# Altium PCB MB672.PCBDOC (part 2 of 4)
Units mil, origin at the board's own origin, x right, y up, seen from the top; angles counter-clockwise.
Board outline 4505 x 6805 mil, 4 copper layers (TopLayer, GND, VCC, BottomLayer); 337 components, 289 nets, 1516 pads, 621 vias.
Unrouted connection lines stored in the file: 46.
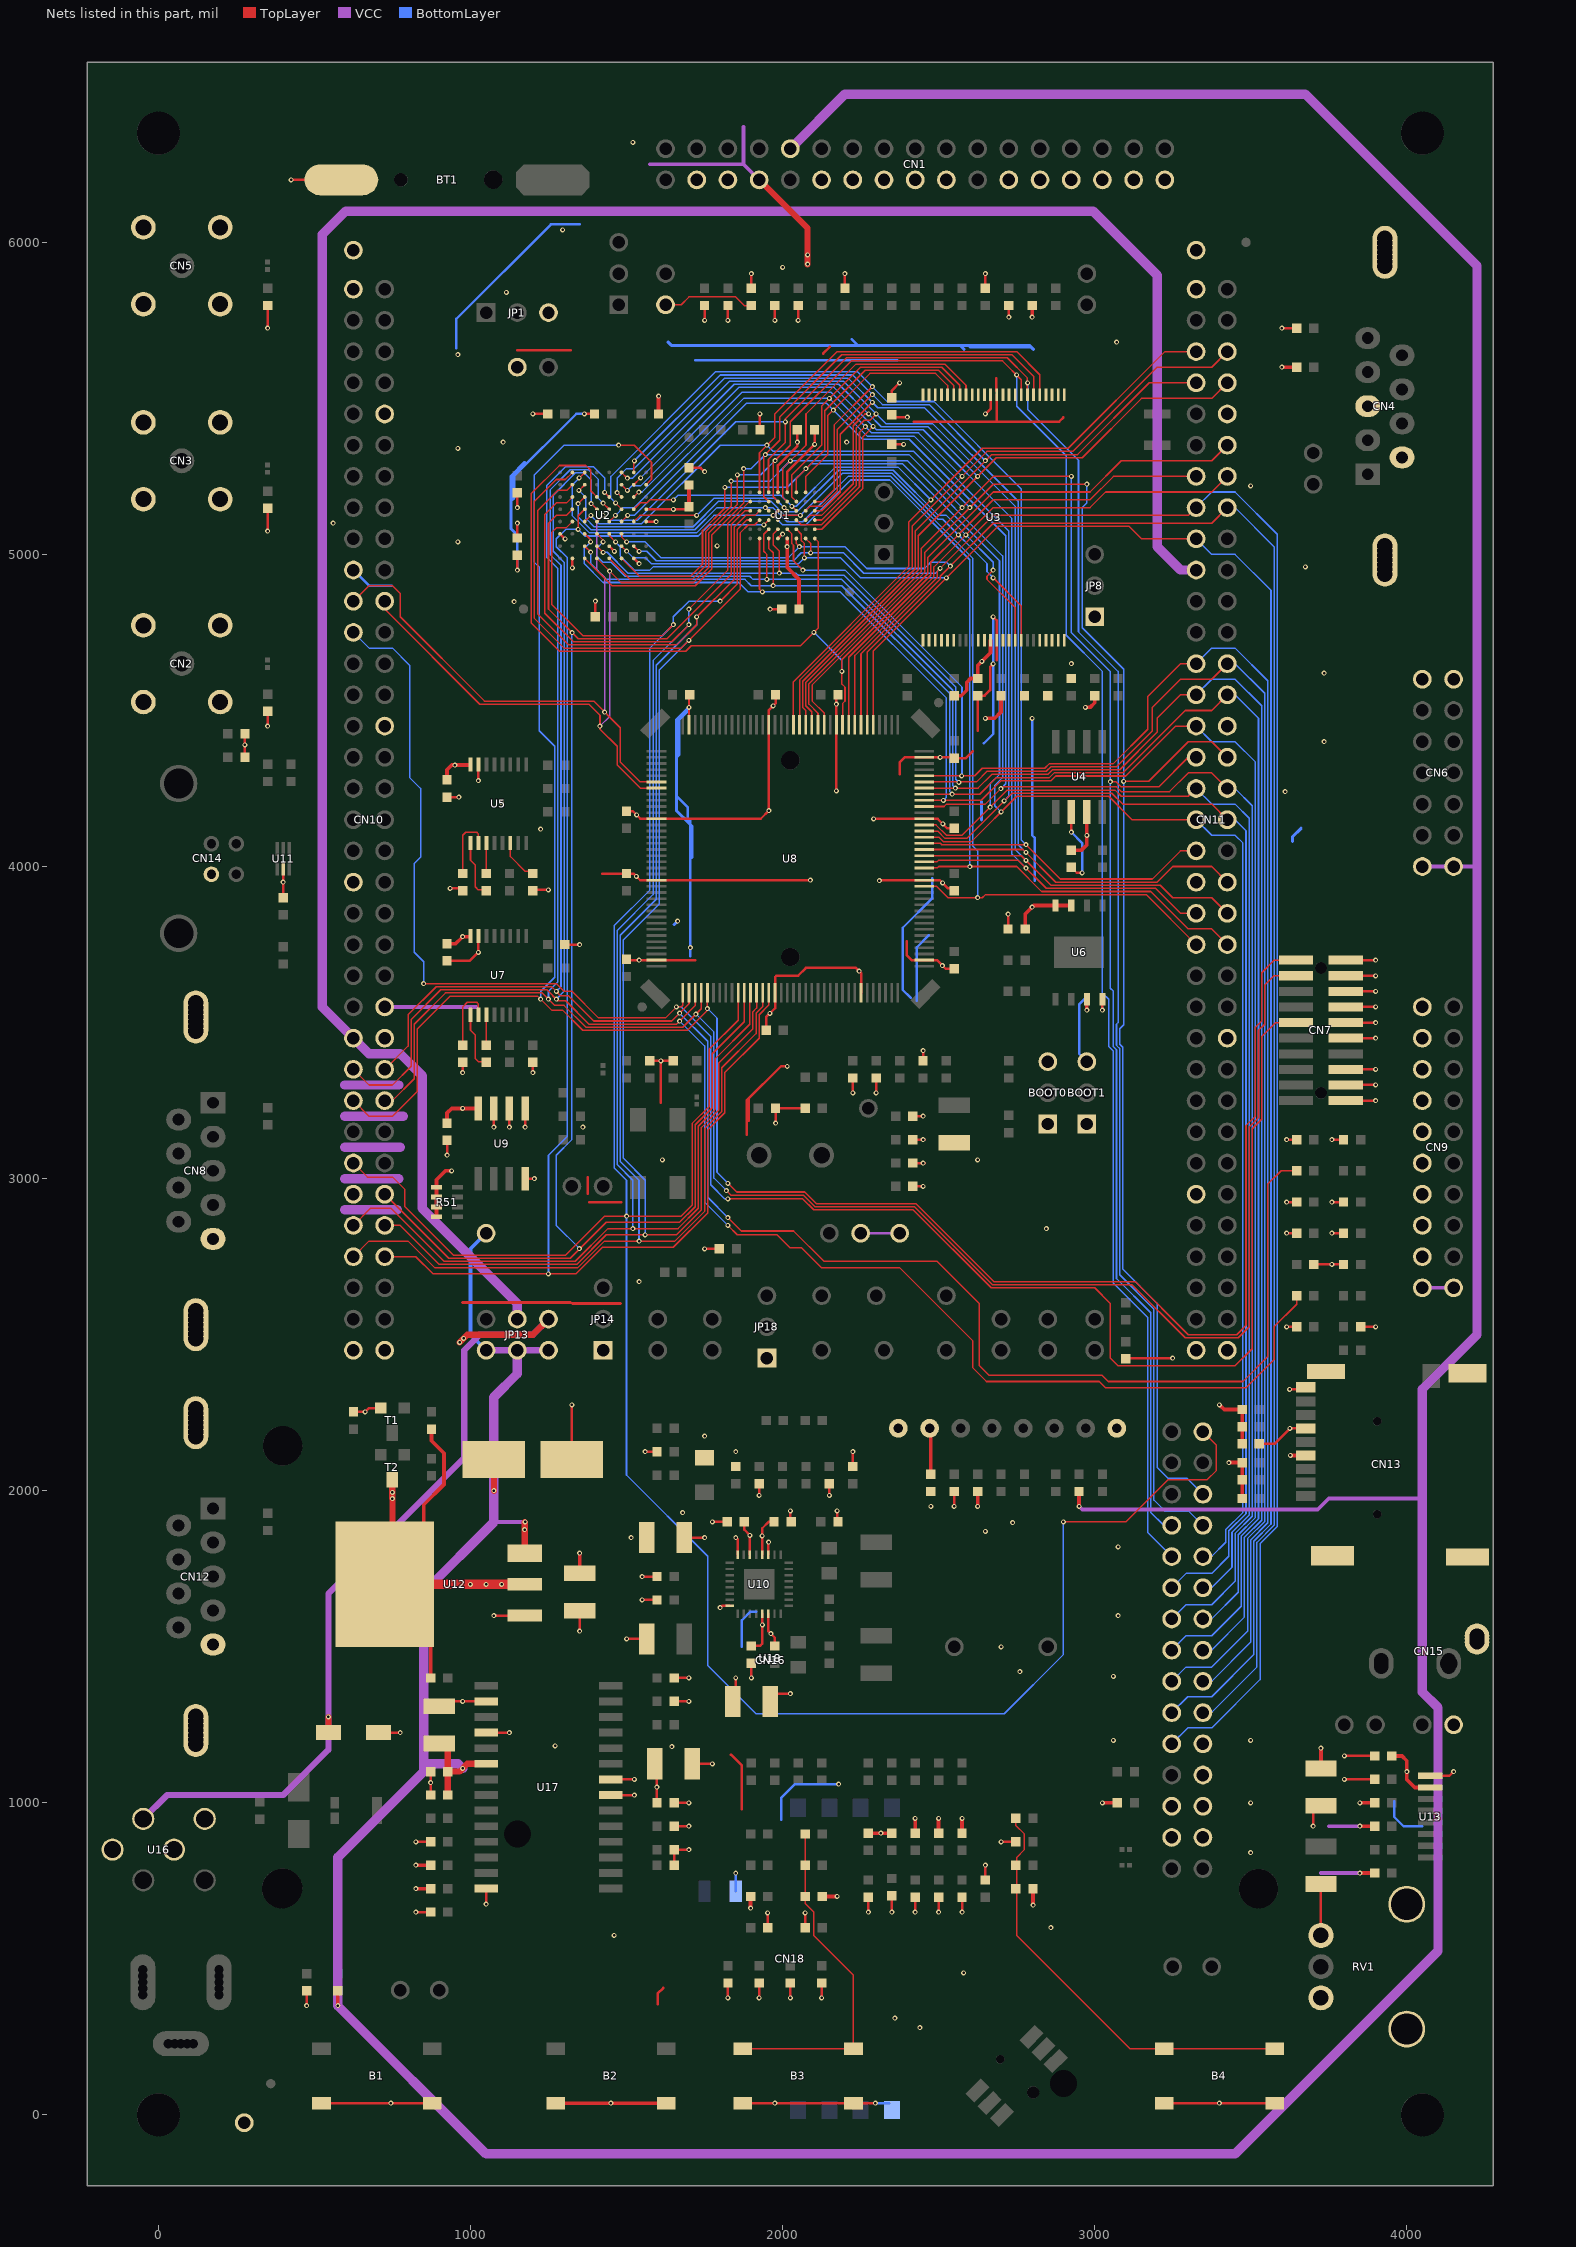
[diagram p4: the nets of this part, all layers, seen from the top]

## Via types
v1: diameter 16, hole 8, TopLayer to BottomLayer, tented both sides, 621 vias

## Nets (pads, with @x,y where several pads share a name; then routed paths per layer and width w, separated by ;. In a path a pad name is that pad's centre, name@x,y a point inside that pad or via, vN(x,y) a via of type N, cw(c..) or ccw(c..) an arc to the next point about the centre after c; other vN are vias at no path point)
+3V3: B2.1 B2.4 BOOT0.1 BOOT1.1 C11.1 C12.1 C14.2 C15.2 C16.1 C20.2 C24.2 C27.2 C34.2 C37.1 C49.2 C52.1 C62.2 C63.2 C64.1 C65.1 C68.1 C69.1 C71.1 C75.2 C79.1 C84.1 C88.2 CN1.28 CN7.1 CN9.1 CN9.2 CN10.48 CN10.69 CN11.69 CN13.4 CN16.24 CN16.25 CN16.28 JP1.3 JP12.2 R7.2 R10.1 R12.1 R13.2 R16.1 R17.2 R18.2 R19.1 R20.2 R23.2 R24.1 R27.2 R51.1 R51.3 R51.5 R51.7 R53.2 R55.2 R58.2 R59.2 R64.2 R66.2 R76.2 R83.2 R85.1 R88.2 R90.1 R91.1 R92.1 R93.1 R107.2 R109.1 R112.2 R113.1 R114.2 R115.2 R116.2 R118.1 R119.2 R120.1 R121.2 R122.2 R130.1 R131.1 R132.1 R133.1 R134.1 RV1.3 T2.3 TP5.1 U1.D6 U1.E1 U2.D8 U2.F1 U2.G5 U3.12 U3.37 U4.3 U5.16 U6.3 U6.7 U6.8 U7.16 U9.8 U10.4 U10.6 U10.8 U10.21 U12.2 U13.7 U17.21 U18.2 | length 8606.8
  TopLayer w8: v1@749.5,1975.5 v1(750,1975) ; C15.2@1150,5045 v1(1150,5100) ; v1(1150,5150) R18.2@1150,5197.5 ; v1(1200,5450) R12.1@1247.5,5450 ; U2.F1@1287.2,5065.94 v1(1303.15,5050) ; R20.2@1400,4800 v1(1400,4850) ; U2.G5@1444.68,5026.57 v1(1461.26,5010) ; U17.21@1450,1025 v1(1525,1025) ; v1(1550,1650) R83.2@1597.5,1650 ; U2.D8@1562.8,5144.69 R19.1@1704.68,5144.68 ; C88.2@1597.5,1000 C84.1@1597.5,1117.5 ; R93.1@1652.5,1325 v1(1700,1325) ; R91.1@1652.5,1400 v1(1700,1400) ; R109.1@1655,925 v1@1702.5,925 ; C65.1@1685,1850 v1(1750,1850) ; C79.1@1850,1340 v1(1850,1400) ; v1(1850,1850) 1856.1,1843.9 U10.8@1856.1,1794.49 ; C62.2@1877.5,1900 1877.5,1875 v1(1895.47,1857.03) U10.6@1895.47,1794.49 ; C75.2@1900,1502.5 1927.5,1502.5 1934.84,1509.84 U10.21@1934.84,1605.51 ; R16.1@1927.5,5400 v1(1927.5,5450) ; U10.4@1934.84,1794.49 1934.84,1879.84 1955,1900 C63.2@1972.5,1900 ; U1.D6@1985.24,5198.82 1985.24,5285.24 2047.5,5347.5 C12.1@2047.5,5400 ; R17.2@2350,5352.5 v1(2387.5,5352.5) ; C11.1@2350,5440 v1(2400,5440) ; v1(2650.1,5450.1) 2666.54,5466.54 U3.37@2666.54,5512.4 ; R58.2@3702.5,2725 R59.2@3797.5,2725 ; v1(3760,2825) R55.2@3797.5,2825 ; v1(3760,2925) R53.2@3797.5,2925 ; CN7.1@3805,3250 v1(3900,3250) ; R64.2@3852.5,2525 v1(3900,2525)
  TopLayer w12: v1(825,725) R119.2@872.5,725 ; v1(825,800) R118.1@872.5,800 ; U12.2@850,1880 850,1955 915,2020 915,2120 875,2160 R66.2@875,2197.5 ; R90.1@872.5,1400 U12.2@872.5,1527.5 ; R51.7@891.5,2877.76 891.5,2996.5 920,3025 v1(940,3025) ; C49.2@925,3177.5 925,3210 940,3225 U9.8@1025,3225 ; C37.1@925,3752.5 952.5,3752.5 v1(975,3775) U7.16@998.03,3775 ; C24.2@925,4277.5 925,4310 940,4325 U5.16@998.03,4325 ; B2.1@1272.83,37.5 B2.4@1627.17,37.5 ; C69.1@1350,1735 v1(1350,1800) ; R13.2@1602.5,5450 v1(1602.5,5507.5) ; R19.1@1700,5152.5 C14.2@1700,5222.5 ; v1(1897.5,662.5) R120.1@1897.5,700 ; U1.E1@2014.76,5051.18 2014.76,4957.74 2052.5,4920 C16.1@2052.5,4825 ; R121.2@2127.5,700 v1(2175,700) ; R112.2@2275,902.5 R113.1@2350,902.5 ; R114.2@2425,902.5 v1(2425,950) ; C64.1@2475,2052.5 U18.2@2475,2196.06 ; R115.2@2500,902.5 v1(2500,950) ; R23.2@2550,4547.5 2572.5,4547.5 2590,4565 2590,4590 2602.5,4602.5 C20.2@2625,4602.5 2625,4643.46 2666.54,4685 U3.12@2666.54,4725 ; R116.2@2575,902.5 v1(2575,950) ; v1(2625,1950) R76.2@2625,1997.5 ; v1(2650,4475) 2680,4475 2700,4495 R24.1@2700,4547.5 ; C34.2@2777.5,3800 2777.5,3847.5 2805,3875 U6.7@2925,3875 ; v1(2800,5760) R7.2@2800,5797.5 ; v1(2802.5,672.5) R122.2@2802.5,725 ; C27.2@2925,4052.5 2957.5,4052.5 2975,4070 U4.3@2975,4175 ; v1(2970,4510) 2985,4510 3000,4525 R27.2@3000,4547.5 ; v1(2975,3540) U6.3@2975,3575 ; v1(3025,1000) R107.2@3072.5,1000 ; v1(3400,2275) 3415,2260 R131.1@3472.5,2260 C52.1@3472.5,2150 ; v1(3430,2090) R134.1@3472.5,2090 R132.1@3472.5,1975 ; v1(3600,5600) R10.1@3647.5,5600 ; v1(3627.01,2112.99) CN13.4@3676.65,2112.99 ; C71.1@3725,1110 v1(3725,1175) ; v1(3850,775) R92.1@3897.5,775 ; v1(3850,925) R88.2@3897.5,925 ; v1(3850,1000) R85.1@3897.5,1000 ; C68.1@3952.5,1150 3985,1150 4000,1135 4000,1075 4025.59,1049.41 U13.7@4075,1049.41
  TopLayer w20: v1@749.5,1975.5 T2.3@749.5,2035 ; U12.2@750,1710 v1(750,1975) ; CN1.28@1925,6200 2080,6045 v1(2080,5930)
  TopLayer w30: U12.2@730,1700 U12.2@1173.82,1700
  VCC w8: JP12.2@2250,2825 TP5.1@2375,2825
  VCC w12: CN10.48@725,3550 1020,3550 ; 1575,6250 1875,6250 ; 1875,6370 1875,6250 ; CN1.28@1925,6200 1875,6250 ; 3725,775 v1(3850,775) ; 3750,925 v1(3850,925) ; CN9.2@4050,2650 CN9.1@4150,2650
  other v1: 1450,37.5 2315,902.5 1700,925 1597.5,1050 4000,1100 1935,1570 1000,1700 1050,1700 1100,1700 1934.84,1855 749.5,1995 3760,2725 975,3225 2800,3870 2975,4100 950,4325 2638.69,4657.15 2014.76,5025 1650,5144.69 2047.5,5360 2080,5960
+5V: C61.1 C82.1 C83.1 C86.1 CN1.25 CN6.1 CN6.2 JP13.1 JP13.3 JP13.5 R79.1 R127.2 TP4.1 U12.3 U17.6 | length 17048.1
  TopLayer w12: v1(575,350) R127.2@575,397.5 ; v1(2950,1950) R79.1@2950,1997.5
  TopLayer w20: C86.1@927.5,1025 C82.1@927.5,1187.5 ; C83.1@927.5,1100 965,1100 990,1125 U17.6@1050,1125 ; v1(1075,2000) C61.1@1075,2100 ; U12.3@1173.82,1800 v1@1173.82,1898.82
  VCC w12: 1075,1900 v1(1175,1900) ; v1(2950,1950) 2960,1940 3715,1940 3750,1975 4050,1975 ; CN6.2@4050,4000 4220,4000
  VCC w20: JP13.1@1050,2450 JP13.5@1250,2450
  VCC w30: 850,1125 960,1125 v1(975,1110) ; JP13.3@1150,2450 1150,2375 1075,2300 1075,1900 850,1675 850,1100 575,825 v1(575,350) 1050,-125 3450,-125 4100,525 4100,1305 4050,1355 4050,2325 4225,2500 4225,5925 3675,6475 2200,6475 CN1.25@2025,6300
  BottomLayer w12: JP13.1@1050,2450 1000,2500 1000,2775 TP4.1@1050,2825
  other v1: 1173.82,1875
A0: CN10.57 CN16.2 U1.A3 U2.E2 U8.10 | length 9253.4
  TopLayer w5: CN10.57@625,3050 670,3005 750,3005 790,2965 790,2910 945,2755 1305,2755 1430,2880 1675,2880 1710,2915 1710,3176.42 1765,3231.42 1765,3415 1857.68,3507.68 U8.10@1857.68,3595.87 ; U2.E2@1326.57,5105.32 1306.26,5085 1275,5085 1260,5070 1260,4840 1360,4740 1615,4740 v1(1649.93,4774.93) ; v1(1800,4850) 1855,4905 1855,5080 1885.24,5110.24 U1.A3@1896.65,5110.24 ; v1(2900,1900) 3100,1900 3235,2035 3360,2035 3390,2065 3390,2146 CN16.2@3347,2189
  BottomLayer w5: v1(1800,4850) 1700,4850 1649.93,4799.93 v1(1649.93,4774.93) 1575,4700 1575,3925 1460,3810 1460,3035 1500,2995 1500,2050 1760,1790 1760,1440 1915,1285 2710,1285 2900,1475 v1(2900,1900)
  other v1: 1500,2880
A1: CN10.60 U1.A4 U2.D2 U8.11 | length 5243.3
  TopLayer w5: CN10.60@725,2950 930,2745 1320,2745 1435,2860 1670,2860 1720,2910 1720,3172.28 1775,3227.28 1775,3400 1877.36,3502.36 U8.11@1877.36,3595.87 ; U2.D2@1326.57,5144.69 1306.89,5125 1275,5125 1250,5100 1250,4825 1345,4730 1630,4730 1835,4935 1835,5095 1879.76,5139.76 U1.A4@1896.65,5139.76
  BottomLayer w5: v1@1325,4748.94 1325,3125 1275,3075 1275,2850 v1(1349.13,2775.87)
  other v1: 1325.53,4749.47
A2: CN10.61 U1.A5 U2.C2 U8.12 | length 5502.1
  TopLayer w5: CN10.61@625,2850 680,2905 745,2905 915,2735 1336,2735 1441,2840 1665,2840 1730,2905 1730,3168.14 1785,3223.14 1785,3385 1895,3495 U8.12@1895,3593.82 ; U2.C2@1326.57,5184.06 1307.52,5165 1275,5165 1238.15,5128.15 1238.15,4811.85 1330,4720 1645,4720 v1(1700,4775) ; v1(1700,4825) 1825,4950 1825,5100 U1.A5@1894.29,5169.29
  BottomLayer w5: v1(1520,2840) 1520,2995 1470,3045 1470,3795 1585,3910 1585,4660 v1(1700,4775) v1(1700,4825)
A3: CN10.62 U1.B3 U2.A2 U8.13 | length 5500.2
  TopLayer w5: CN10.62@725,2850 775,2850 900,2725 1340.15,2725 1435.15,2820 1660,2820 1740,2900 1740,3164 1795,3219 1795,3370 1905,3480 1905,3535 1916.73,3546.73 U8.13@1916.73,3595.87 ; U2.A2@1326.57,5262.8 1303.78,5240 1275,5240 1205,5170 1205,4795 1300,4700 1675,4700 1865,4890 1865,5070 1890,5095 1910.94,5095 U1.B3@1926.18,5110.24
  BottomLayer w5: v1(1560,2820) 1560,2995 1490,3065 1490,3765 1605,3880 1605,4630 v1(1700,4725)
A4: CN10.63 U1.B4 U2.B2 U8.14 | length 5679.8
  TopLayer w5: CN10.63@625,2750 675,2800 800,2800 885,2715 1344.29,2715 1429.29,2800 1655,2800 1750,2895 1750,3159.85 1805,3214.85 1805,3355 1915,3465 1915,3530 1936.42,3551.42 U8.14@1936.42,3595.87 ; U2.B2@1326.57,5223.43 1308.15,5205 1280,5205 1215,5140 1215,4810 1315,4710 1660,4710 1725,4775 v1(1725,4800) 1845,4920 1845,5088.11 1881.89,5125 1911.42,5125 U1.B4@1926.18,5139.76
  BottomLayer w5: v1(1540,2800) 1540,2995 1480,3055 1480,3780 1595,3895 1595,4645 1725,4775 v1(1725,4800)
A5: CN10.64 U1.C3 U2.D3 U8.15 | length 5116.4
  TopLayer w5: CN10.64@725,2750 825,2750 880,2695 1338.43,2695 1423.43,2780 1650,2780 1760,2890 1760,3155.71 1815,3210.71 1815,3340 1925,3450 1925,3525 1956.1,3556.1 U8.15@1956.1,3595.87 ; v1(1345,5080) 1345,5123.74 U2.D3@1365.94,5144.69 ; v1(1940.47,5095) U1.C3@1955.71,5110.24
  BottomLayer w5: v1(1250,2695) 1250,3075 1310,3135 1310,4990 1275,5025 1275,5050 1305,5080 v1(1345,5080) 1366,5059 1730,5059 1766,5095 v1(1940.47,5095)
A6: CN11.43 U1.C4 U2.C3 U8.50 | length 3635.7
  TopLayer w5: v1(1345,5163.11) U2.C3@1365.94,5184.06 ; v1(1945,5150) U1.C4@1955.24,5139.76 ; U8.50@2454.13,3936.42 2493.58,3936.42 2530,3900 2640,3900 2650,3910 3165,3910 CN11.43@3325,3750
  BottomLayer w5: v1(1345,5163.11) 1345,5120 1386,5079 1719,5079 1790,5150 1968.94,5150 2013.94,5105 2065,5105 2210,5250 2346.72,5250 2610,4986.72 2610,4065 2625,4050 v1(2625,3900)
A7: CN11.44 U1.D4 U2.A3 U8.53 | length 3732.5
  TopLayer w5: v1(1348.15,5245) U2.A3@1365.94,5262.8 ; v1@1970.47,5125 U1.D4@1985.24,5139.76 ; U8.53@2454.13,3995.47 2495.47,3995.47 2500,4000 2750,4000 2830,3920 3180,3920 3300,3800 3375,3800 CN11.44@3425,3750
  BottomLayer w5: v1(1348.15,5245) 1326.57,5223.43 1326.57,5123.43 1381,5069 1724,5069 1780,5125 v1(1970,5125) 2000,5095 2075,5095 2218.57,5238.57 2344.01,5238.57 2600,4982.57 v1(2600,4000)
A8: CN11.41 U1.H2 U2.B6 U8.54 | length 4070.6
  TopLayer w5: U2.B6@1484.06,5223.43 v1(1502.48,5205) ; U1.H2@2103.35,5080.71 2125.71,5080.71 2256.54,5211.54 2256.54,5376.54 v1(2290,5410) ; U8.54@2454.13,4015.16 2495,4015.16 2499.52,4019.67 2755.33,4019.67 2845,3930 3195,3930 3275,3850 CN11.41@3325,3850
  BottomLayer w5: v1(1502.48,5205) 1517.1,5219.61 1544.61,5219.61 1860,5535 2165,5535 2300.8,5399.2 2450.8,5399.2 2735,5115 2735,4040 v1(2780,3995)
A9: CN11.42 U1.H3 U2.A6 U8.55 | length 4204.7
  TopLayer w5: U2.A6@1484.06,5262.8 v1(1502.48,5244.37) ; U1.H3@2103.35,5110.24 2125.24,5110.24 2236.54,5221.54 2236.54,5405 2261.4,5429.86 2279.86,5429.86 v1(2300.01,5449.99) ; U8.55@2454.13,4034.84 2765.16,4034.84 2860,3940 3210,3940 3250,3900 3375,3900 CN11.42@3425,3850
  BottomLayer w5: v1(1502.48,5244.37) 1519.37,5244.37 1830,5555 2195,5555 2330.8,5419.2 2480.8,5419.2 2745,5155 2745,4055 v1(2780,4020)
A10: CN11.40 U1.H4 U2.C6 U8.56 | length 4275.8
  TopLayer w5: v1(1470,5198.11) U2.C6@1484.06,5184.06 ; U1.H4@2103.35,5139.76 2125.62,5139.76 2185,5199.14 2185,5385 v1@2287.39,5487.39 ; U8.56@2454.13,4054.53 2770.47,4054.53 2875,3950 3200,3950 3250,4000 3375,4000 CN11.40@3425,3950
  BottomLayer w5: v1(1470,5198.11) 1470,5245 1500,5275 1525,5275 1815,5565 2210,5565 2305,5470 2455,5470 2755,5170 2755,4070 v1(2780,4045)
  other v1: 2287.61,5487.39
A11: CN11.37 U1.H5 U2.D6 U8.57 | length 4288.4
  TopLayer w5: v1(1465,5165) 1484.06,5145.94 U2.D6@1484.06,5144.69 ; U1.H5@2103.35,5169.29 2126.86,5169.29 2165,5207.43 2165,5415 v1(2287.5,5537.5) ; U8.57@2454.13,4074.21 2505.79,4074.21 2510,4070 v1(2780,4070) 2890,3960 3185,3960 3275,4050 CN11.37@3325,4050
  BottomLayer w5: v1(1465,5165) 1450,5180 1450,5250 1785,5585 2240,5585 2335,5490 2485,5490 2765,5210 2765,4085 v1(2780,4070)
A12: CN11.8 U1.G3 U2.B7 U8.87 | length 3764
  TopLayer w5: U2.B7@1523.43,5223.43 v1(1545,5245) ; U1.G3@2073.82,5110.24 2088.58,5125 2125,5125 2226.54,5226.54 2226.54,5412.39 2264.14,5450 v1(2275.39,5450) ; U8.87@2093.9,4454.13 2093.9,4496.1 2074.53,4515.47 2074.53,4589.67 2435,4950.15 2435,5060 2685,5310 2960,5310 3150,5500 3375,5500 CN11.8@3425,5550
  BottomLayer w5: v1(1545,5245) 1845,5545 2180,5545 v1@2275,5450 ; v1@2275.2,5449.8 2315.8,5409.2 2465.8,5409.2 v1(2625,5250)
A13: CN11.7 U1.G4 U2.A7 U8.88 | length 3742.4
  TopLayer w5: U2.A7@1523.43,5262.8 v1@1523.43,5298.43 ; U1.G4@2073.82,5139.76 2089.06,5155 2126.72,5155 2175,5203.28 2175,5400 v1@2287.21,5512.21 ; U8.88@2074.21,4454.13 2074.21,4500 2064.53,4509.68 2064.53,4593.82 2425,4954.29 2425,5075 2670,5320 2945,5320 3175,5550 CN11.7@3325,5550
  BottomLayer w5: v1(1525,5300) 1800,5575 2225,5575 2320,5480 2470,5480 2649.8,5300.2 v1(2650.2,5300.2)
  other v1: 2287.79,5512.21
A14: CN11.6 U1.F3 U2.C7 U8.89 | length 3789.6
  TopLayer w5: U2.C7@1523.43,5184.06 v1(1539.37,5200) ; U1.F3@2044.29,5110.24 2059.53,5095 2125,5095 2246.54,5216.54 2246.54,5391.24 v1@2265.16,5409.86 ; U8.89@2054.53,4454.13 2054.53,4597.96 2415,4958.43 2415,5090 2655,5330 2930,5330 3200,5600 3375,5600 CN11.6@3425,5650
  BottomLayer w5: v1(1539.37,5200) 1550,5200 1870,5520 2155,5520 2285.8,5389.2 2435.8,5389.2 v1(2575,5250)
  other v1: 2265.16,5409.84
A15: CN11.5 U1.F4 U2.D7 U8.90 | length 3052
  TopLayer w5: U2.D7@1523.43,5144.69 1543.74,5165 1565,5165 1575,5175 v1(1650,5175) ; v1(2030,5154.06) U1.F4@2044.29,5139.76 U1.F4@2044.29,5140.71 ; U8.90@2034.84,4454.13 2034.84,4592.42 2405,4962.57 2405,5105 2640,5340 2915,5340 3225,5650 CN11.5@3325,5650
  BottomLayer w5: v1(1650,5175) 1665,5190 1994.06,5190 v1(2030,5154.06) 2043.53,5154.06 2169.48,5280 2370,5280 v1(2475,5175)
A16: CN11.14 U1.E4 U2.E7 U3.16 U8.80 | length 3358.3
  TopLayer w5: U2.E7@1523.43,5105.32 1543.11,5125 v1(1725,5125) ; v1(2005,5150) 2014.76,5140.24 U1.E4@2014.76,5139.76 ; U8.80@2231.69,4454.13 2231.69,4676.13 2485,4929.44 2485,4960 2675,5150 2985,5150 3035,5200 3375,5200 CN11.14@3425,5250 ; v1(2675,4950) 2655,4930 2655,4920 2745.28,4829.72 U3.16@2745.28,4725
  BottomLayer w5: v1(1725,5125) 1780,5180 1975,5180 2017.78,5137.22 2047.22,5137.22 2180,5270 2355,5270 2500,5125 2525.01,5125 v1(2587.5,5062.5) 2675,4975 v1(2675,4950)
A17: CN11.13 U1.D3 U2.B3 U3.17 U8.81 | length 3611.8
  TopLayer w5: v1(1347.52,5205) U2.B3@1365.94,5223.43 ; U1.D3@1985.24,5110.24 2000,5125 v1(2057,5125) ; U8.81@2212.01,4454.13 2212.01,4670.59 2475,4933.58 2475,4974.56 v1(2563.09,5062.65) ; v1@2562.87,5062.87 2675,5175 2985,5175 3060,5250 CN11.13@3325,5250 ; v1(2675,4925) 2764.96,4835.04 U3.17@2764.96,4725
  BottomLayer w5: v1(1347.52,5205) 1370,5182.52 1370,5115 1396,5089 1714,5089 1795,5170 1963.08,5170 2008.08,5125 v1(2057,5125) 2192,5260 2350.86,5260 2498.01,5112.85 2512.89,5112.85 2655,4970.74 2655,4945 v1(2675,4925)
A18: CN11.12 U1.H1 U2.C4 U8.82 | length 3951
  TopLayer w5: U2.C4@1405.31,5184.06 1385,5204.37 1385,5270 1370,5285 1285,5285 1195,5195 1195,4780 1285,4690 1690,4690 1707.54,4707.54 2057.54,4707.54 2115,4765 2115,5039.53 U1.H1@2103.35,5051.18 ; U8.82@2192.32,4454.13 2192.32,4522.32 2200,4530 2200,4575 2190,4585 2190,4662.72 2465,4937.72 2465,4990 2675,5200 2985,5200 3085,5300 3375,5300 CN11.12@3425,5350
  BottomLayer w5: v1(2100.52,4750.52) 2190,4661.05 v1(2190,4625)
A19: CN10.52 R49.2 U2.D5 U8.2 | length 6656.8
  TopLayer w5: CN10.52@725,3350 800,3425 800,3525 890,3615 1260,3615 v1@1274,3601 ; v1(1275,3600) 1288.85,3586.15 1313.85,3586.15 1395,3505 1645,3505 v1(1670,3530) ; v1(1425,5164.37) U2.D5@1444.68,5144.69 ; v1@1670.1,3529.9 1700.2,3560 U8.2@1700.2,3595.87 ; v1(1825,2875) 1867.82,2832.18 2035.25,2832.18 2132.43,2735 2495,2735 2630,2600 2630,2401.57 2661.57,2370 3023.28,2370 3043.28,2350 3475,2350 3555,2430 3555,2982.5 3597.5,3025 R49.2@3647.5,3025
  BottomLayer w5: v1(1275,3600) 1290,3615 1290,4965 1255,5000 1255,5206.52 1320,5271.52 1378.48,5271.52 1410,5240 1410,5179.37 v1(1425,5164.37) ; v1(1670,3530) 1760,3440 1760,2940 v1(1825,2875)
A20: CN10.51 R60.2 U2.D4 U8.3 | length 6351
  TopLayer w5: CN10.51@625,3350 675,3300 750,3300 810,3360 810,3510 905,3605 1245,3605 1280,3570 1305,3570 1380,3495 1660,3495 1719.88,3554.88 U8.3@1719.88,3595.87 ; v1(1386.86,5163.14) U2.D4@1405.32,5144.68 ; v1(1825,2850) 1855,2820 1982.18,2820 2024.02,2778.16 2060.98,2778.16 2124.14,2715 2375,2715 2610,2480 2610,2393.28 2653.28,2350 3015,2350 3035,2330 3485,2330 3575,2420 3575,2525 3647.5,2597.5 R60.2@3647.5,2625
  BottomLayer w5: v1(1275,3575) 1300,3600 1300,4975 1265,5010 1265,5190 1336.52,5261.52 1363.48,5261.52 1386.86,5238.14 v1(1386.86,5163.14) ; v1(1670,3505) 1750,3425 1750,2925 v1(1825,2850)
A21: CN7.18 CN10.54 U2.C5 U8.4 | length 7066
  TopLayer w5: CN10.54@725,3250 750,3250 820,3320 820,3495 920,3595 1230,3595 1270,3555 1300,3555 1370,3485 1680,3485 1739.57,3544.57 U8.4@1739.57,3595.87 ; v1(1430,5198.74) U2.C5@1444.68,5184.06 ; v1(1820,2961.79) 1834.72,2947.07 2067.07,2947.07 2104.14,2910 2422.43,2910 2672.43,2660 3120,2660 3290,2490 3460,2490 3495,2525 3495,3165 3525,3195 3525,3475 3545,3495 3545,3620 3575,3650 CN7.18@3645,3650
  BottomLayer w5: v1(1250,3575) 1250,3600 1280,3630 1280,4955 1245,4990 1245,5221.52 1305,5281.52 1393.48,5281.52 1430,5245 v1(1430,5198.74) ; v1(1722.37,3527.37) 1780,3469.74 1780,3001.79 v1(1820,2961.79)
A22: CN7.20 CN10.53 U2.B8 U8.5 | length 7540.5
  TopLayer w5: CN10.53@625,3250 675,3200 750,3200 830,3280 830,3480 935,3585 1215,3585 1259.85,3540.15 1294.85,3540.15 1360,3475 1695,3475 1759.25,3539.25 U8.5@1759.25,3595.87 ; v1(1475,5350) 1525,5350 1580,5295 1580,5240.63 U2.B8@1562.8,5223.43 ; v1(1825,2985) 1852.93,2957.07 2071.21,2957.07 2108.28,2920 2426.57,2920 2676.57,2670 3130,2670 3300,2500 3455,2500 3485,2530 3485,3170 3515,3200 3515,3485 3535,3505 3535,3660 3575,3700 CN7.20@3645,3700
  BottomLayer w5: v1(1225,3575) 1225,3600 1270,3645 1270,4385 1220,4435 1220,4960 1203.91,4976.09 1203.91,5253.91 1300,5350 v1(1475,5350) ; v1(1759.25,3545) 1790,3514.25 1790,3020 v1(1825,2985)
A23: CN7.12 CN10.23 U8.1 | length 6077.9
  TopLayer w5: v1(850,3625) 1275,3625 1300,3600 1325,3600 1410,3515 1625,3515 v1(1660,3550) 1675,3550 1680.51,3555.51 U8.1@1680.51,3595.87 ; v1(1825,2935) 2065,2935 2100,2900 2418.28,2900 2668.28,2650 3000,2650 3050,2600 3050,2425 3075,2400 3450,2400 3505,2455 3505,3160 3535,3190 3535,3455 3580,3500 CN7.12@3645,3500
  BottomLayer w5: CN10.23@625,4750 675,4700 750,4700 805,4645 805,4285 840,4250 840,4030 820,4010 820,3725 850,3695 v1(850,3625) ; v1(1660,3550) 1675,3550 1770,3455 1770,2980 1815,2935 v1(1825,2935)
D0: CN11.32 CN16.6 U1.B6 U2.E3 U3.29 U8.85 | length 7918.9
  TopLayer w5: U2.E3@1365.94,5105.32 v1(1385.63,5125) ; U1.B6@1926.18,5198.82 1926.18,5326.18 1975,5375 1975,5450 2175,5650 2750,5650 2824.02,5575.98 U3.29@2824.02,5512.4 ; U8.85@2133.27,4454.13 2133.27,4491.73 2094.53,4530.47 2094.53,4581.39 2455,4941.86 2455,5005 2675,5225 v1(2975,5225) ; v1(3093.14,4273.14) 3173.14,4273.14 3300,4400 3375,4400 CN11.32@3425,4350
  BottomLayer w5: v1(1385.63,5125) 1411.63,5099 1549,5099 1800,5350 v1(1950,5350) 1970,5330 2420,5330 v1(2600,5150) ; v1(2975,5225) 2975,5165 2960,5150 2960,4765 3093.14,4631.86 3093.14,3493.14 3080,3480 3080,3430.86 3090,3420.86 3090,2710 3200,2600 3200,2075 3235,2040 3296,2040 CN16.6@3347,1989
D1: CN11.31 CN16.7 U1.C5 U2.H3 U3.30 U8.86 | length 8033.4
  TopLayer w5: U2.H3@1365.94,4987.2 1453.15,4900 1720,4900 1773.46,4953.46 1773.46,5062.61 1875,5164.14 v1(1875,5275) ; U1.C5@1955.71,5169.29 1940,5185 1940,5315 1990.61,5365.61 1990.61,5440.61 2190,5640 2735,5640 2804.33,5570.67 U3.30@2804.33,5512.4 ; U8.86@2113.58,4454.13 2113.58,4491.42 2084.53,4520.47 2084.53,4585.53 2445,4946 2445,5020 2675,5250 v1(2925,5250) ; v1(3050,4271.72) 3068.28,4271.72 3085,4255 3205,4255 3300,4350 CN11.31@3325,4350
  BottomLayer w5: v1(1875,5275) 1900,5275 v1(1944.69,5319.69) ; v1@1945,5320 2405,5320 v1(2575,5150) ; v1(2925,5250) 2925,4750 3050,4625 3050,3610 3060,3600 3060,3422.57 3070,3412.57 3070,2680 3180,2570 3180,1930 3221,1889 CN16.7@3247,1889
D2: CN10.21 CN16.8 U1.C6 U2.E4 U3.31 U8.114 | length 7894
  TopLayer w5: CN10.21@625,4850 675,4900 750,4900 775,4875 775,4800 1045,4530 1395,4530 1480,4445 1480,4335 1543.94,4271.06 U8.114@1595.87,4271.06 ; U2.E4@1405.32,5105.32 v1(1425,5125) ; U1.C6@1955,5199.53 1955,5305 2008.64,5358.64 2008.64,5433.64 2205,5630 2720,5630 2784.65,5565.35 U3.31@2784.65,5512.4
  VCC w5: v1(1425,5125) 1405,5105 1405,4950 1430,4925 v1(1430,4495)
  BottomLayer w5: v1(1425,5125) 1441,5109 1534,5109 1850,5425 v1(2008.64,5425) ; v1(2785,5550) 2785,5465 2948.2,5301.8 2948.2,4751.8 3075,4625 3075,3500 3070,3495 3070,3426.72 3080,3416.72 3080,2691.72 3190,2581.72 3190,1970 3225,1935 3301,1935 CN16.8@3347,1889
D3: CN10.22 CN16.9 U1.D5 U2.H4 U3.32 U8.115 | length 7758.6
  TopLayer w5: CN10.22@725,4850 725,4825 1030,4520 1380,4520 1414.94,4485.06 1414.94,4440.06 1470,4385 1470,4325 1543.62,4251.38 U8.115@1595.87,4251.38 ; U2.H4@1405.31,4987.2 1482.52,4910 1715,4910 1763.46,4958.46 1763.46,5068.46 1855,5160 v1(1855,5255) ; U1.D5@1985.24,5169.29 1970,5184.53 1970,5295 2025,5350 2025,5425 2220,5620 2705,5620 2764.96,5560.04 U3.32@2764.96,5512.4
  VCC w5: v1(1414.94,4450) 1446.03,4481.09 v1(1446.03,4946.49)
  BottomLayer w5: v1(1855,5255) 1930,5255 v1(1975.8,5300.8) ; v1(2750,5575) 2750,5475 2908.63,5316.37 2908.63,4741.37 3025,4625 3025,3595 3045,3575 3045,3423.43 3060,3408.43 3060,2665 3170,2555 3170,1866 CN16.9@3247,1789
D4: CN11.35 CN16.10 U1.E5 U2.H5 U3.41 U8.58 | length 6980.3
  TopLayer w5: U2.H5@1444.68,4987.2 1511.89,4920 1710,4920 1753.46,4963.46 1753.46,5072.61 1835,5154.14 v1(1835,5235) ; U1.E5@2014.76,5169.29 2000,5184.06 2000,5275 2075,5350 2075,5450 2235,5610 2520,5610 2587.8,5542.2 U3.41@2587.8,5512.4 ; U8.58@2454.13,4093.9 2501.1,4093.9 2515,4080 2605,4080 2750,4225 3045,4225 3120,4150 CN11.35@3325,4150
  BottomLayer w5: v1(1835,5235) 1960,5235 v1(2025,5300) 2400,5300 2705,4995 2705,4285 2680,4260 2680,4195 v1(2700,4175) ; CN11.35@3325,4150 3375,4100 3450,4100 3475,4075 3475,1930.56 3420,1875.56 3420,1835 3374,1789 CN16.10@3347,1789
D5: CN11.36 CN16.11 U1.F5 U2.E5 U3.42 U8.59 | length 7113.5
  TopLayer w5: U2.E5@1444.68,5105.32 v1(1464.37,5125) ; U1.F5@2044.29,5169.29 2030,5183.58 2030,5255 2125,5350 2125,5475 2250,5600 2510,5600 2568.11,5541.89 U3.42@2568.11,5512.4 ; U8.59@2454.13,4113.58 2497.28,4113.58 2520.86,4090 2590,4090 2735,4235 3055,4235 3090,4200 3375,4200 CN11.36@3425,4150
  BottomLayer w5: v1(1464.37,5125) 1489.37,5150 1525,5150 1875,5500 v1(2150,5500) 2270.8,5379.2 2420.8,5379.2 2725,5075 2725,4225 v1(2710,4210) ; CN16.11@3247,1689 3293,1735 3375,1735 3430,1790 3430,1871.42 3485,1926.42 3485,4115 3450,4150 CN11.36@3425,4150
D5V: CN10.49 CN11.19 JP13.4 | length 8491.5
  VCC w30: 596.61,2900 765,2900 ; 596.61,3000 770,3000 ; 596.61,3100 775,3100 ; 596.61,3200 785,3200 ; 596.61,3300 770,3300 ; JP13.4@1150,2550 1150,2600 845,2905 845,3330 775,3400 675,3400 525,3550 525,6025 600,6100 2995,6100 3200,5895 3200,5025 3275,4950 CN11.19@3325,4950
D6: CN11.33 CN16.12 U1.F6 U2.H6 U3.43 U8.60 | length 6948.7
  TopLayer w5: U2.H6@1484.06,4987.2 1541.26,4930 1705,4930 1743.46,4968.46 1743.46,5076.75 1815,5148.28 v1(1815,5215) ; U1.F6@2044.29,5198.82 2044.29,5244.29 2135,5335 2135,5460 2265,5590 2500,5590 2548.43,5541.57 U3.43@2548.43,5512.4 ; U8.60@2454.13,4133.27 2491.73,4133.27 2525,4100 2575,4100 2720,4245 3065,4245 3085,4225 3300,4225 CN11.33@3325,4250
  BottomLayer w5: v1(1815,5215) 2015,5215 2090,5290 2385,5290 2695,4980 2695,4295 2665,4265 v1(2665,4190) ; v1@2074.27,5275 v1(2074.64,5274.64) ; CN11.33@3325,4250 3375,4200 3450,4200 3495,4155 3495,1922.28 3440,1867.28 3440,1755 3374,1689 CN16.12@3347,1689
D7: CN11.34 CN16.13 U1.G6 U2.E6 U3.44 U8.63 | length 7053.2
  TopLayer w5: U2.E6@1484.06,5105.32 v1(1503.74,5125) ; U1.G6@2073.82,5198.82 2073.82,5248.82 2145,5320 2145,5445 2280,5580 2490,5580 2528.74,5541.26 U3.44@2528.74,5512.4 ; U8.63@2454.13,4192.32 2517.32,4192.32 2525,4200 2650,4200 2705,4255 3070,4255 3085,4240 3240,4240 3300,4300 3375,4300 CN11.34@3425,4250
  BottomLayer w5: v1(1503.74,5125) 1525,5125 1885,5485 2139.93,5485 2255.73,5369.2 2405.8,5369.2 2715,5060 2715,4265 v1(2699.83,4249.83) ; CN16.13@3247,1589 3293,1635 3375,1635 3450,1710 3450,1863.14 3505,1918.14 3505,4195 3450,4250 CN11.34@3425,4250
  other v1: 2162.47,5462.47
D8: CN11.29 CN16.14 U1.B1 U2.F3 U8.64 | length 5995.7
  TopLayer w5: U2.F3@1365.94,5065.94 1385,5046.89 v1(1385,5040) ; U1.B1@1926.18,5051.18 1926.18,4888.82 v1(1935,4880) ; U8.64@2454.13,4212.01 2637.01,4212.01 2700,4275 2860,4275 2875,4290 3100,4290 3260,4450 CN11.29@3325,4450
  BottomLayer w5: v1(1385,5040) 1365,5020 1365,4970 1425,4910 1860,4910 1890,4880 2185,4880 2525,4540 2525,4222.01 v1(2515,4212.01) ; CN11.29@3325,4450 3375,4400 3450,4400 3515,4335 3515,1914 3460,1859 3460,1675 3374,1589 CN16.14@3347,1589
D9: CN11.28 CN16.15 U1.C1 U2.G3 U8.65 | length 6253.2
  TopLayer w5: U2.G3@1365.94,5026.57 v1(1385,5007.52) ; U1.C1@1955.71,5051.18 1955.71,5019.29 1970,5005 v1(1970,4900) ; U8.65@2454.13,4231.69 2631.69,4231.69 2685,4285 2855,4285 2870,4300 3090,4300 3290,4500 3375,4500 CN11.28@3425,4550
  BottomLayer w5: v1(1385,5007.52) 1385,4970 1435,4920 1880,4920 1900,4900 2190,4900 2535,4555 2535,4240 v1(2543.31,4231.69) ; CN16.15@3247,1489 3293,1535 3375,1535 3470,1630 3470,1854.85 3525,1909.85 3525,4475 3450,4550 CN11.28@3425,4550
D10: CN11.27 CN16.16 U1.C2 U2.F4 U8.66 | length 6300.6
  TopLayer w5: U2.F4@1405.31,5065.94 1425,5046.26 v1(1425,5040) ; v1(1950,4920) 1950,5000 1940,5010 1940,5065 U1.C2@1955.71,5080.71 ; U8.66@2454.13,4251.38 2626.38,4251.38 2670,4295 2850,4295 2865,4310 3080,4310 3200,4430 3200,4475 3275,4550 CN11.27@3325,4550
  BottomLayer w5: v1(1425,5040) 1405,5020 1405,4995 1425,4975 1450,4975 1495,4930 1895,4930 1905,4920 2190,4920 2545,4565 2545,4260 v1(2553.62,4251.38) ; CN11.27@3325,4550 3375,4600 3450,4600 3535,4515 3535,1905.71 3480,1850.71 3480,1595 3374,1489 CN16.16@3347,1489
D11: CN11.26 CN16.17 U1.D2 U2.G4 U8.67 | length 6469.8
  TopLayer w5: U2.G4@1405.31,5026.57 v1(1425,5006.89) ; U1.D2@1985.24,5080.71 1970,5065.47 1970,5030 1990,5010 v1(1990,4940) ; U8.67@2454.13,4271.06 2621.06,4271.06 2655,4305 2845,4305 2860,4320 3070,4320 3185,4435 3185,4510 3275,4600 3375,4600 CN11.26@3425,4650
  BottomLayer w5: v1(1425,5006.89) 1438.11,5006.89 1505,4940 2043.39,4940 2050,4933.39 2196.61,4933.39 2555,4575 2555,4280 v1(2565,4270) ; CN16.17@3247,1389 3293,1435 3375,1435 3490,1550 3490,1846.57 3545,1901.57 3545,4555 3450,4650 CN11.26@3425,4650
D12: CN11.25 CN16.18 U1.E2 U2.F5 U8.68 | length 6482
  TopLayer w5: U2.F5@1444.68,5065.94 1444.68,5060.32 v1(1465,5040) ; U1.E2@2014.76,5080.71 2030,5065.47 2030,5035 2035,5030 2035,4980 v1(2065,4950) ; U8.68@2454.13,4290.75 2615.75,4290.75 2640,4315 2840,4315 2855,4330 3060,4330 3170,4440 3170,4545 3275,4650 CN11.25@3325,4650
  BottomLayer w5: v1(1465,5040) 1480,5025 1480,4995 1525,4950 1575,4950 1585,4960 2055,4960 v1(2065,4950) 2200,4950 2575,4575 v1@2575,4290.75 ; CN11.25@3325,4650 3375,4700 3450,4700 3555,4595 3555,1897.43 3500,1842.43 3500,1515 3374,1389 CN16.18@3347,1389
  other v1: 2574,4290.75
D13: CN11.17 CN16.19 U1.F2 U2.G6 U8.77 | length 6735.1
  TopLayer w5: U2.G6@1484.06,5026.57 v1(1500,5010.63) ; U1.F2@2044.29,5080.71 2060,5065 2060,5045 2070,5035 v1(2070,4989.21) ; U8.77@2290.75,4454.13 2290.75,4690.75 2690,5090 3110,5090 3150,5050 CN11.17@3325,5050
  BottomLayer w5: v1(1500,5010.63) 1520.63,4990 1560,4990 1580,4970 2050.79,4970 v1(2070,4989.21) 2185.79,4989.21 2250,4925 v1(2525,4925) ; CN16.19@3247,1289 3298,1340 3375,1340 3510,1475 3510,1838.28 3565,1893.28 3565,4885 3450,5000 3375,5000 CN11.17@3325,5050
D14: CN11.16 CN16.20 U1.F1 U2.F6 U8.78 | length 6809.7
  TopLayer w5: U2.F6@1484.06,5065.94 1484.06,5055.94 v1(1500,5040) ; U1.F1@2044.29,5051.18 2044.29,5034.71 v1(2054,5025) ; U8.78@2271.06,4454.13 2271.06,4687.21 2505,4921.15 2505,4930 v1@2537.5,4962.5 ; v1(2537.33,4962.67) 2537.67,4962.67 2675,5100 3375,5100 CN11.16@3425,5150
  BottomLayer w5: v1(1500,5040) 1560,5040 1610,4990 2019,4990 v1(2054,5025) 2200,5025 2270,4955 2455,4955 2475,4975 2525,4975 v1(2537.33,4962.67) ; CN16.20@3347,1289 3374,1289 3520,1435 3520,1834.14 3575,1889.14 3575,5025 3450,5150 CN11.16@3425,5150
D15: CN11.15 CN16.21 U1.G1 U2.G7 U8.79 | length 7001.7
  TopLayer w5: U2.G7@1523.43,5026.57 v1(1540,5010) ; U1.G1@2073.82,5051.18 2090,5035 v1(2090,5005) ; U8.79@2251.38,4454.13 2251.38,4681.67 2495,4925.29 2495,4945 2675,5125 3300,5125 CN11.15@3325,5150
  BottomLayer w5: v1(1540,5010) 1565,5010 1595,4980 2035,4980 2060,5005 2195,5005 2260,4940 2490,4940 v1(2505,4955) ; CN16.21@3247,1189 3298,1240 3375,1240 3530,1395 3530,1830 3585,1885 3585,5065 3450,5200 3375,5200 CN11.15@3325,5150
E5V: C81.1 JP13.6 U16.3 | length 2822.9
  TopLayer w20: C81.1@545,1225 v1(545,1275) ; v1(965,2475) 990,2500 1200,2500 JP13.6@1250,2550
  VCC w20: U16.3@-48.43,948.43 28.15,1025 400,1025 545,1170 545,1670 980,2105 980,2450 1030,2500 1200,2500 JP13.6@1250,2550
  other v1: 977.86,2487.86
GND: B1.1 B1.4 B3.1 B3.4 B4.1 B4.4 BOOT0.3 BOOT1.3 BT1.2 C1.1 C2.1 C3.1 C4.1 C5.1 C6.1 C7.1 C8.1 C9.1 C10.2 C11.2 C12.2 C13.1 C14.1 C15.1 C16.2 C17.2 C18.2 C19.2 C20.1 C21.1 C22.1 C23.2 C24.1 C25.2 C26.2 C27.1 C28.1 C31.1 C32.2 C33.2 C34.1 C35.2 C36.2 C37.2 C38.2 C39.1 C42.1 C43.2 C44.2 C45.2 C46.1 C47.2 C48.2 C49.1 C50.2 C51.1 C52.2 C53.2 C54.2 C55.1 C58.1 C59.2 C60.1 C61.2 C62.1 C63.1 C64.2 C65.2 C66.2 C68.2 C69.2 C71.2 C72.2 C73.2 C74.1 C75.1 C77.2 C78.1 C79.2 C81.2 C82.2 C83.2 C84.2 C86.2 C88.1 C89.2 C90.1 C94.1 C95.1 C96.1 C97.1 C98.1 C99.1 C100.1 CN1.2 CN1.4 CN1.6 CN1.8 CN1.10 CN1.12 CN1.16 CN1.18 CN1.20 CN1.22 CN1.24 CN1.30 CN1.32 CN2.1 CN2.2 CN2.3 CN2.4 CN3.1 CN3.2 CN3.3 CN3.4 CN4.0 CN4.3 CN4.6 CN5.1 CN5.2 CN5.3 CN5.4 CN6.13 CN6.14 CN7.3 CN7.5 CN7.9 CN7.11 CN7.13 CN7.15 CN7.17 CN7.19 CN8.0 CN8.5 CN9.4 CN9.6 CN9.8 CN9.10 CN9.12 CN9.14 CN9.16 CN9.18 CN9.20 CN10.1 CN10.10 CN10.19 CN10.30 CN10.39 CN10.50 CN10.59 CN10.70 CN11.1 CN11.10 CN11.30 CN11.39 CN11.50 CN11.59 CN11.70 CN12.0 CN12.5 CN13.6 CN13.9 CN13.G1 CN13.G2 CN13.G3 CN13.G4 CN14.4 CN15.1 CN16.22 CN16.26 CN16.27 CN18.5 CN18.17 JP5.1 JP8.1 JP14.1 JP18.1 JP21.2 LD1.2 LD2.2 LD3.2 LD4.2 LD5.2 R9.1 R25.2 R26.2 R34.2 R41.2 R47.2 R48.2 R52.1 R54.1 R63.1 R65.2 R72.2 R73.2 R74.1 R86.2 R95.1 R108.2 R117.1 R123.2 R124.1 R125.1 R136.2 R137.2 R138.2 RV1.0 RV1.1 T1.1 TP1.1 TP2.1 TP16.1 U1.D1 U1.E6 U2.E8 U2.H2 U2.H7 U3.13 U3.36 U4.2 U5.15 U6.4 U7.15 U8.16 U8.30 U8.38 U8.51 U8.61 U8.71 U8.83 U8.94 U8.107 U8.120 U8.130 U8.143 U9.4 U9.5 U9.6 U9.7 U10.3 U10.16 U10.22 U11.2 U12.1 U13.8 U16.4 U16.5 U16.6 U17.2 U17.4 U17.14 U17.22 U18.1 U18.8 | length 23142.7
  TopLayer w8: R95.1@277.5,4350 C78.1@277.5,4425 ; v1(350,4450) R136.2@350,4497.5 ; v1(350,5075) R137.2@350,5147.5 ; v1(350,5725) R138.2@350,5797.5 ; C74.1@400,3900 U11.2@400,3993.7 ; v1(425,6200) BT1.2@586.42,6200 ; v1(475,350) LD5.2@475,397.5 ; B1.1@522.83,37.5 B1.4@877.17,37.5 ; R65.2@625,2252.5 v1(662.5,2252.5) 675,2265 T1.1@712.5,2265 ; C81.2@705,1225 v1(775,1225) ; v1(825,650) C94.1@872.5,650 ; v1(825,875) C89.2@872.5,875 ; C86.2@872.5,1025 C83.2@872.5,1100 ; C82.2@885,1325 U17.2@1050,1325 ; v1(925,3075) C49.1@925,3122.5 ; C37.2@925,3697.5 997.5,3697.5 1025.59,3725.59 U7.15@1025.59,3776.97 ; C24.1@925,4222.5 v1(962.5,4222.5) ; v1(935,3930) C28.1@972.5,3930 ; v1(975,3340) C39.1@975,3372.5 ; v1(1025,4275) 1025.59,4275.59 U5.15@1025.59,4326.97 ; v1(1050,675) U17.14@1050,725 ; U17.4@1050,1225 v1(1125,1225) ; v1(1075,1600) U12.1@1173.82,1600 ; v1(1075,3165) U9.7@1075,3225 ; v1(1125,3165) U9.6@1125,3225 ; v1(1150,4950) C15.1@1150,4997.5 ; 1150,5655 1321.39,5655 ; U9.4@1175,3000 v1(1205,3000) ; v1(1175,3165) U9.5@1175,3225 ; v1(1200,3340) C42.1@1200,3372.5 ; C31.1@1202.5,3925 v1(1250,3925) ; R34.2@1302.5,3750 v1(1350,3750) ; C61.2@1325,2100 v1(1325,2275) ; v1(1326.57,4956.57) U2.H2@1326.57,4987.2 ; v1(1350,1550) C69.2@1350,1615 ; v1(1365,5450) C10.2@1397.5,5450 ; 1375,2952.09 1375,3005 ; 1380,2925 1483.92,2925 ; 1422.5,3977.5 1522.5,3977.5 1543.9,3956.1 v1(2088.9,3956.1) ; U17.22@1450,1075 v1(1525,1075) ; v1(1500,1525) C73.2@1565,1525 ; C25.2@1500,4177.5 1520,4177.5 1544.55,4152.95 1930.16,4152.95 v1(1956.1,4178.9) 1956.1,4501.1 1977.5,4522.5 C18.2@1977.5,4550 ; C35.2@1500.2,3700.2 1719.8,3700.2 ; U2.H7@1523.43,4987.2 v1(1540,4970.63) ; v1(1550,1725) C66.2@1597.5,1725 ; v1(1560,2125) R72.2@1597.5,2125 ; U2.E8@1562.8,5105.32 v1(1595,5105.32) ; C43.2@1575,3377.5 C44.2@1650,3377.5 ; 1599.67,355 1599.67,388.56 1618.29,407.18 ; 1610,3242.4 v1(1610,3377.5) ; C88.1@1650,1000 v1@1697.5,1000 ; C90.1@1652.5,800 R108.2@1652.5,850 v1(1700,850) ; C14.1@1700,5277.5 1737.5,5277.5 v1(1750,5265) ; U8.107@1700.2,4454.13 C17.2@1700.2,4547.7 ; C84.2@1710,1125 v1(1775,1125) ; v1(1750,2775) C60.1@1797.5,2775 ; v1(1750,5750) C1.1@1750,5797.5 ; v1(1775,1900) C62.1@1822.5,1900 ; v1(1800,1625) 1806.1,1631.1 U10.16@1830.51,1631.1 ; v1(1825,375) LD4.2@1825,422.5 ; v1(1825,5750) C3.1@1825,5797.5 ; 1834.36,1154.53 1870,1118.89 1870,980 ; B3.1@1872.83,37.5 v1(2297.5,37.5) ; 1885,3140 1885,3250 1995,3360 v1(2015,3360) ; 1892.04,3185 1892.04,3257.04 ; v1(1900,1400) C75.1@1900,1450 ; C2.1@1900,5852.5 v1(1900,5900) ; v1(1925,375) LD3.2@1925,422.5 ; v1(1925,1985) C55.1@1925,2022.5 ; C38.2@1947.5,3475 1947.5,3517.5 1975.79,3545.79 1975.79,3645.79 1980,3650 2050,3650 2075,3675 2235,3675 2251.38,3658.62 U8.30@2251.38,3595.87 ; R123.2@1952.5,600 v1(1952.5,647.5) ; U10.22@1954.53,1605.51 1954.53,1550 v1(1962.21,1542.32) 1975,1529.53 R86.2@1975,1502.5 ; U10.3@1954.53,1794.49 1954.53,1834.53 v1(1955,1835) ; C79.2@1960,1350 v1(2025,1350) ; v1(1960,4825) C16.2@1997.5,4825 ; v1(1975,5750) C4.1@1975,5797.5 ; v1(1977.5,3177.5) C47.2@1977.5,3225 C48.2@2072.5,3225 ; U1.D1@1985.24,5051.18 1999.06,5065 v1(2000,5065) ; U1.E6@2014.76,5198.82 2014.76,5264.76 v1(2102.5,5352.5) C12.2@2102.5,5400 ; v1(2025,375) LD2.2@2025,422.5 ; C63.1@2025,1902.5 v1(2025,1935) ; v1(2050,5750) C5.1@2050,5797.5 ; R124.1@2072.5,600 v1(2072.5,647.5) ; v1(2125,375) LD1.2@2125,422.5 ; 2129.82,5643.71 2151.11,5665 ; v1(2150,1985) C58.1@2150,2022.5 ; v1(2172.64,4242.64) C19.2@2172.64,4545.14 ; R73.2@2175,1902.5 v1(2175,1935) ; C6.1@2200,5852.5 v1(2200,5900) ; C59.2@2225,2077.5 v1(2225,2125) ; v1(2225,3275) R41.2@2225,3322.5 ; v1(2275,650) C95.1@2275,697.5 ; v1(2292.05,4152.95) 2497.05,4152.95 2527.5,4122.5 C26.2@2550,4122.5 ; v1(2300,3275) C45.2@2300,3322.5 ; v1(2310,3955) 2311.1,3956.1 2503.9,3956.1 2530,3930 C33.2@2545,3930 ; v1(2350,650) C96.1@2350,702.5 ; C11.2@2350,5502.5 2350,5525 v1(2375,5550) ; 2375,4295 2375,4333.74 2391.07,4349.8 C23.2@2547.7,4349.8 ; 2397.64,3760 2397.64,3716.25 2413.69,3700.2 2494.8,3700.2 2522.5,3672.5 C36.2@2550,3672.5 ; R63.1@2417.5,2975 v1(2450,2975) ; C22.1@2417.5,3050 v1@2455,3050 ; C13.1@2417.5,3125 v1@2455,3125 ; C9.1@2417.5,3200 v1(2450,3200) ; 2420.08,5425 2886.11,5425 2900,5438.89 ; v1(2425,650) C97.1@2425,697.5 ; C46.1@2450,3377.5 v1(2450,3410) ; v1(2500,650) C98.1@2500,697.5 ; v1(2550,1950) R74.1@2550,1997.5 ; C23.2@2550,4347.5 2587.5,4347.5 2610,4370 ; v1(2575,650) C99.1@2575,697.5 ; 2625,4435 C20.1@2625,4547.5 2647.5,4547.5 2665,4565 2665,4639.62 v1(2674.95,4649.58) ; R125.1@2650,752.5 v1(2650,800) ; C7.1@2650,5852.5 v1(2650,5900) ; v1(2675,4800) 2686.22,4788.78 2686.22,4661.22 ; U3.36@2685,5525 2685,5565 ; 2686.22,5425 U3.36@2686.22,5512.4 ; v1(2700,875) R117.1@2747.5,875 ; C34.1@2722.5,3800 v1(2722.5,3847.5) ; v1(2725,5760) C8.1@2725,5797.5 ; v1@2735,1897.5 v1(2737.5,1897.5) ; C27.1@2925,3997.5 2942.5,3980 v1(2960,3980) ; v1(2925,4110) U4.2@2925,4175 ; v1(3025,3540) U6.4@3025,3575 ; C100.1@3102.5,2425 v1(3250,2425) ; B4.1@3222.83,37.5 B4.4@3577.17,37.5 ; C52.2@3527.5,2150 3575.79,2150 v1(3625.39,2199.61) CN13.6@3676.65,2199.61 ; v1(3600,5725) R9.1@3647.5,5725 ; v1(3615,2525) C51.1@3647.5,2525 ; v1(3615,2825) R54.1@3647.5,2825 ; v1(3615,2925) R52.1@3647.5,2925 ; v1(3615,3125) R47.2@3647.5,3125 ; v1(3625,2325) CN13.9@3675,2325 ; v1(3700,925) C71.2@3700,985 ; RV1.1@3725,575 C77.2@3725,740 ; v1(3760,3125) R48.2@3797.5,3125 ; v1(3800,1075) C72.2@3897.5,1075 ; v1(3800,1150) C68.2@3897.5,1150 ; CN7.3@3805,3300 v1(3900,3300) ; CN7.5@3805,3350 v1(3900,3350) ; CN7.9@3805,3450 v1(3900,3450) ; CN7.11@3805,3500 v1(3900,3500) ; CN7.13@3805,3550 v1(3900,3550) ; CN7.15@3805,3600 v1(3900,3600) ; CN7.17@3805,3650 v1(3900,3650) ; CN7.19@3805,3700 v1(3900,3700) ; U13.8@4075,1086.81 4136.81,1086.81 v1(4150,1100)
  TopLayer w10: 975,2602.5 1320,2602.5 ; 1327.5,2600 1480,2600
  BottomLayer w8: CN10.19@625,4950 675,4900 747.91,4900 ; 954.39,5660 954.39,5754.39 1257.5,6057.5 1350,6057.5 ; 1129,5083.38 1150,5062.38 v1(1150,4950) ; 1130,5241.11 1338.89,5450 v1(1365,5450) ; v1(1700.2,4510) 1660,4469.8 1660,4226.11 1695.61,4190.5 1695.61,4155 1705,4145.61 1705,3712.5 ; 1720,5622.5 2367.5,5622.5 ; CN18.17@1850,716.54 v1(1850,775) ; 1870,1500 1870,1585 1897.5,1612.5 1915,1612.5 ; 1995,945 1995,1015 2040,1060 v1(2180,1060) ; v1(2205,5360) v1@2210,5360 ; 2221.09,5690.02 2241.11,5670 2585,5670 ; v1(2297.5,37.5) CN18.5@2342.5,37.5 ; 2410,3580 2385,3605 2385,3803.68 2480,3898.68 2480,3962.04 ; 2430,3570 2430,3741.11 2468.89,3780 ; 2645,4395 2674.95,4424.95 v1(2675,4800) ; v1(2800,4475) 2800,4100 2807.5,4092.5 2807.5,3955 ; v1@2925,4105.98 v1(2925,4110) 2960,4075 v1(2960,3980) ; 2972.5,3580 2950,3557.5 2950,3400 BOOT1.3@2975,3375 ; 3960,1005 3960,955 3990,925 4050,925
  BottomLayer w10: 1130,5171 1139.43,5180.43 1139.43,5250.53 ; 1150,5062.38 1130,5082.38 1130,5251.11 1173.74,5294.85 ; 1633.89,5680 1643.89,5670 2791.11,5670 2803.61,5657.5 ; 1652.94,3814.05 v1(1663.89,3825) v1@1665,3825 ; 1660,4335 1660,4469.8 v1(1700.2,4510) ; 1697.86,4500 1667.5,4469.64 1667.5,4357.5 1660,4350 1660,4178.89 1703.89,4135 1705,4135 ; 1709.89,4029.89 1709.89,4129 ; 2545,5670 2568.89,5670 2581.39,5657.5 ; 2637.5,4150 2637.5,4208.24 ; 2792.5,5665 2600,5665 ; 3633.55,4080 3633.55,4094.66 3661.73,4122.84 ; 2600,5665 2600,5670 2600,5665
  other v1: 745,37.5 1975,37.5 3400,37.5 2440,280 2360,310 2580,455 1460,575 2860,600 3500,840 1700,1000 3500,1000 872.5,1065 1645,1180 1271.41,1182.52 3060,1200 3500,1200 975,1325 3060,1405 2760,1420 2700,1500 3075,1600 3075,1820 1515,1850 2650,1870 1680,1930 2475,1950 1850,2125 1750,2175 1540,2670 2845,2840 2450,3050 1615,3060 2625,3060 2450,3125 1360,3165 1959.5,3529.5 2245,3665 2512.24,3682.76 1540,3700.2 1025,3725 1705,3740 2512.5,3947.5 400,3950 1531.8,3968.2 1225,4120 2513.45,4136.55 1532.31,4165.19 1100,4205 3610,4240 2505,4349.8 277.5,4390 3735,4400 1969.87,4514.87 2172.64,4520 3735,4620 2925,4650 1140,4848.89 3675,4960 1790,5027.5 960,5040 560,5100 3500,5220 960,5340 1105,5360 960,5640 3070,5680 1115,5840 2000,5920 1295,6040 1520,6320
NC: U3.1 U3.2 U3.3 U3.4 U3.5 U3.6 U3.10 U3.11 U3.14 U3.15 U3.20 U3.21 U3.22 U3.23 U3.24 U3.25 U3.26 U3.27 U3.28 U3.33 U3.34 U3.35 U3.38 U3.39 U3.40 U3.45 U3.46 U3.47 U3.48
NetB3_2: B3.2 B3.3 C92.2 R111.1 R121.1 | length 1105.9
  TopLayer w5: B3.2@1872.83,212.5 B3.3@2227.17,212.5 2227.17,447.83 2100,575 2100,650 2072.5,677.5 R111.1@2072.5,900
NetB4_2: B4.2 B4.3 C93.2 R106.1 R122.1 | length 1374.1
  TopLayer w5: R106.1@2747.5,950 2747.5,927.5 2775,900 2775,850 2750,825 2750,575 3112.5,212.5 B4.3@3577.17,212.5
NetC2_2: C2.2 JP2.2 | length 296.7
  TopLayer w5: JP2.2@1625,5800 1675,5800 1700,5825 1850,5825 1877.5,5797.5 C2.2@1900,5797.5
NetC28_2: C28.2 U5.2 | length 209
  TopLayer w5: C28.2@975,3977.5 975,4100 985,4110 1020,4110 1025.59,4104.41 U5.2@1025.59,4075
NetC29_1: C29.1 U5.1 | length 182.9
  TopLayer w5: U5.1@1000,4075 1000,4020 1015,4005 1015,3935 1025,3925 C29.1@1047.5,3925
NetC29_2: C29.2 U5.3 | length 96.3
  TopLayer w5: C29.2@1050,3977.5 U5.3@1050,4073.82
NetC31_2: C31.2 U5.6 | length 134.5
  TopLayer w5: U5.6@1127.95,4075 1127.95,4032.05 1175,3985 C31.2@1200,3985
NetC39_2: C39.2 U7.2 | length 216
  TopLayer w5: C39.2@975,3427.5 975,3550 990,3565 1020,3565 1025.59,3559.41 U7.2@1025.59,3525
NetC41_1: C41.1 U7.1 | length 182.9
  TopLayer w5: U7.1@1000,3525 1000,3475 1015,3460 1015,3385 1025,3375 C41.1@1047.5,3375
NetC41_2: C41.2 U7.3 | length 96.3
  TopLayer w5: C41.2@1051.18,3428.68 U7.3@1051.18,3525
